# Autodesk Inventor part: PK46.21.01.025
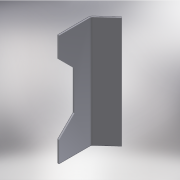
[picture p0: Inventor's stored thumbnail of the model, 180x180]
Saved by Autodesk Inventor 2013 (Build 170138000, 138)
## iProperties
Created: 2005-04
Part Number: PK46.21.01.025
Material: Steel, Mild
Document SubType Name: Sheet Metal
Designer: salex
Manufacturer: Standard
Standards Organization: Custom
Density: 7.86 g/cm^3
Sheet Metal Rule: Default
Author: salex
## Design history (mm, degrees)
node "ФлнОтгиб1"
sketch "Эскиз2"
  geometry: L1 (0, 223.327)-(0, 0); L2 (0, 0)-(800, 0); L3 (800, 0)-(800, 223.327); L4 (150, 0)-(260, 110); L5 (260, 110)-(540, 110); L6 (540, 110)-(650, 0); L7 (800, 221.178)-(0, 221.178) reference; L8 (0, 221.178)-(0, 0) reference; L9 (0, 0)-(800, 0) reference; L10 (800, 0)-(800, 221.178) reference
  constraints: 12 end point, 2 perpendicular, 2 point on line
  dimensions: "d11" = 110 distance between parallel lines of L5 L2; "d12" = 150 distance from line of L4.start L1; "d13" = 260 distance from line of L4.end L1; "d14" = 150 distance from line of L6.end L3 (= d12)
extrude "Выдавливание1" cut sketch "Эскиз2" stored distance "d15" = 10; taper "d16" = 0 deg
body "Solid1"
sketch "Эскиз1"
  geometry: L1 (-0.232, 229.772)-(114.768, 334.772); L2 (-0.232, 229.772)-(-0.232, -0.228)
  constraints: 4 end point, 1 vertical, 1 other
  dimensions: "d24" = 230 distance of L1.start L2.end; "d25" = 335 vertical distance of L2.end L1.end; "d26" = 115 horizontal distance of L1.start L1.end
feature "Плакирование1" dims "d4" = 800, "d5" = 10 (= BendReliefWidth), "d7" = 20 (= MinimumRemnant), "d9" = 20 (= BendRadius), "d10" = 10, "Thickness" = 10
feature "Изгиб1" dims "d5" = 10 (= BendReliefWidth), "d6" = 5 (= BendReliefDepth), "d7" = 20 (= MinimumRemnant), "d8" = 20 (= BendRadius), "d9" = 20 (= BendRadius), "d10" = 10, "SeamGap" = 0.01, "Thickness" = 10
other parameters: "BendRadius" = 20, "BendReliefDepth" = 5 (= 0.5 x Thickness), "d2" = 335, "d18" = 225, "d20" = 225
